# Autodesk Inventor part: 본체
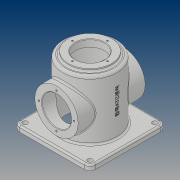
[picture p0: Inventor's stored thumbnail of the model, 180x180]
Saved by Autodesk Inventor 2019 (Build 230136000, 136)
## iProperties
Created: 2019-03
Part Number: 본체
Material: 일반
Document SubType Name: Modeling
Designer: PC312-11
Density: 1 g/cm^3
Appearance: 기본값
Author: PC312-11
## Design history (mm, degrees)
sketch "스케치1"
  geometry: L1 (50, 0)-(50, 120); L2 (27, 125)-(27, 112); L3 (27, 112)-(45, 112); L4 (45, 112)-(45, 0); L5 (45, 0)-(50, 0); L6 (0, 0)-(0, 125); L7 (50, 120)-(40, 120); L8 (40, 120)-(40, 125); L9 (40, 125)-(27, 125)
  constraints: 18 end point, 5 vertical, 4 horizontal, 2 point on line
  dimensions: "d0" = 90 diameter of L4 L6; "d1" = 100 diameter of L1 L6; "d3" = 54 diameter of L2 L6; "d4" = 112 distance between parallel lines of L5 L3; "d7" = 125 distance between parallel lines of L5 L9; "d8" = 120 distance between parallel lines of L5 L7; "d9" = 80 diameter of L8 L6
revolve "회전1" sketch "스케치1" stored, may be unused: angle "d10" = 90 deg
sketch "스케치2"
  geometry: L1 (-70, 70)-(70, 70); L2 (70, 70)-(70, -70); L3 (70, -70)-(-70, -70); L4 (-70, -70)-(-70, 70); L5 (-70, 70)-(70, -70); L6 (70, 70)-(-70, -70); C1 r 45 at (0, 0) reference; 1 further point
  constraints: 12 end point, 2 midpoint, 2 parallel, 1 horizontal, 1 perpendicular
  dimensions: "d11" = 140 distance of L2.end L3.end; "d12" = 140 distance of L1.end L2.end
extrude "돌출1" join sketch "스케치2" distance "d13" = 10; taper "d14" = 0 deg
node "작업 평면1"
sketch "스케치3"
  geometry: L1 (-70, 0)-(70, 0) reference; C1 r 40 at (0, 60); 2 further points
  constraints: 1 centre point, 1 midpoint, 1 vertical alignment
  dimensions: "d16" = 80 diameter of C1; "d17" = 60 distance from line of L1 C1.centre
extrude "돌출2" join sketch "스케치3" stored distance "d18" = 10; taper "d19" = 0 deg
sketch "스케치4" dims "d20" = 65
  geometry: C1 r 40 at (0, 0) reference; 3 further points
  constraints: 2 vertical alignment, 1 coincident, 2 other
hole "구멍1" sketch "스케치4" at (0, 32.5) diameter "d21" = 3.242; stored, may be unused: countersink angle "d25" = 90 deg, drill point angle "d27" = 118 deg; dims "d22" = 8, "d23" = 4, "d24" = 2, "d26" = 10
sketch "스케치5" dims "d31" = 65
  geometry: 3 further points
  constraints: 2 horizontal alignment, 1 coincident, 2 other
hole "구멍2" sketch "스케치5" at (-32.5, 0) diameter "d32" = 3.242; stored, may be unused: countersink angle "d36" = 90 deg, drill point angle "d38" = 118 deg; dims "d33" = 8, "d34" = 4, "d35" = 2, "d37" = 10
sketch "스케치6"
  geometry: C1 r 40 at (0, 0) reference; 2 further points
  constraints: 1 coincident
hole "구멍3" sketch "스케치6" at (0, 0) diameter "d42" = 54; stored, may be unused: countersink angle "d46" = 90 deg, drill point angle "d48" = 118 deg; dims "d43" = 8, "d44" = 4, "d45" = 2, "d47" = 10
fillet "모깎기1" dims "d49" = 10
sketch "스케치7"
  geometry: A1 r 10 centre (60, -60) between (60, -70) and (70, -60) reference; A2 r 10 centre (60, 60) between (70, 60) and (60, 70) reference; A3 r 10 centre (-60, -60) between (-70, -60) and (-60, -70) reference; A4 r 10 centre (-60, 60) between (-60, 70) and (-70, 60) reference; 5 further points
  constraints: 4 coincident
hole "구멍4" sketch "스케치7" at (60, -60), (60, 60), (-60, -60), (-60, 60) diameter "d50" = 9; stored, may be unused: countersink angle "d54" = 90 deg, drill point angle "d56" = 118 deg; dims "d51" = 8, "d52" = 4, "d53" = 2, "d55" = 10
fillet "모깎기2" dims "d57" = 3
chamfer "모따기1" distance "d58" = 1; stored, may be unused: second distance "d59" = 2, angle "d60" = 45 deg
fillet "모깎기3" dims "d69" = 3
fillet "모깎기4" dims "d70" = 5
node "작업 평면2"
sketch "스케치8"
  geometry: L1 (0, 60)-(0, -60) reference; 3 further points
  constraints: 1 horizontal alignment, 1 midpoint, 1 other
  dimensions: "d62" = 70 distance from line of L1 point (70, 0)
feature "엠보싱1" sketch "스케치8" dims "d0" = 90, "d1" = 100, "d3" = 54, "d4" = 112, "d7" = 125, "d8" = 120, "d9" = 80, "d63" = 0.5, "d64" = 0
node "솔리드1"
pattern_circular "원형 패턴1" dims angle "d29" = 360 deg
mirror "미러1"
pattern_circular "원형 패턴2" dims angle "d40" = 360 deg
other parameters: "d15" = 62, "d61" = 87, "d65" = 0.5, "d66" = 2, "d67" = 0
